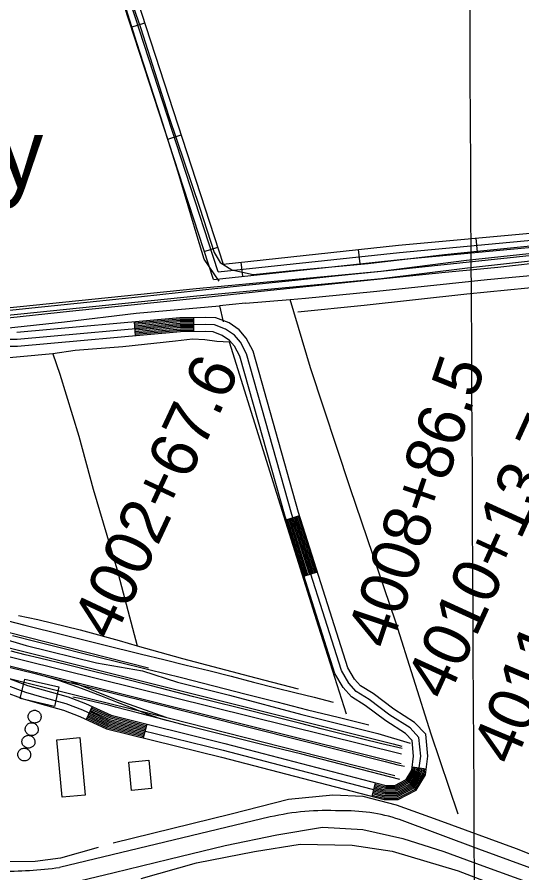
# Model space of a CAD drawing. Extents: x 3445503 to 3483459, y 540493 to 566012.
# Drawn here: x 3469745 to 3470815, y 553015 to 554828 of the extents above; entities that cross this region are included whole.
import ezdxf

# ---------------------------------------------------------------- set-up
doc = ezdxf.new("R2010")
doc.units = 0
for name, color, linetype in [('V-BLDG-OTLN', 7, 'Continuous'), ('V-DOMW-TANK', 7, 'Continuous'), ('V-DTCH-CNTR', 7, 'Continuous'), ('V-GRID-MAJR', 7, 'Continuous'), ('V-LEVE-TOET', 7, 'Continuous'), ('V-RAIL-TRAK', 7, 'Continuous'), ('V-ROAD-CNTR', 7, 'Continuous'), ('V-SURV-IDEN', 7, 'Continuous'), ('V-TOPO-GNAM-IDEN', 7, 'Continuous'), ('V-TOPO-SHOR', 7, 'Continuous')]:
    doc.layers.add(name, color=color, linetype=linetype)

msp = doc.modelspace()

# ---------------------------------------------------------------- linework, layer by layer
at = {"layer": 'V-BLDG-OTLN'}
for points in [[(3469833.551, 553408.933), (3469824.194, 553367.526), (3469751.713, 553383.908), (3469761.756, 553425.157)], [(3469878.085, 553301.382), (3469889.384, 553179.4180000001), (3469840.723, 553174.91), (3469829.4220000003, 553296.8740000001)], [(3470024.412, 553253.463), (3470030.055, 553193.448), (3469987.647, 553189.461), (3469982.006, 553249.478)]]:
    msp.add_lwpolyline(points, close=True, dxfattribs=at)
at = {"layer": 'V-DOMW-TANK'}
for points in [[(3469795.739, 553343.35), (3469795.751, 553341.414), (3469795.057, 553339.837), (3469794.174, 553338.359), (3469793.117, 553337.001), (3469791.901, 553335.778), (3469790.545, 553334.713), (3469789.068, 553333.827), (3469787.494, 553333.1240000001), (3469785.847, 553332.622), (3469784.149, 553332.325), (3469782.429, 553332.2390000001), (3469780.711, 553332.3640000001), (3469779.019, 553332.698), (3469777.383, 553333.2390000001), (3469775.824, 553333.974), (3469774.3680000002, 553334.894), (3469773.037, 553335.987), (3469771.847, 553337.234), (3469770.821, 553338.6190000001), (3469769.971, 553340.118), (3469769.311, 553341.709), (3469768.853, 553343.37), (3469768.599, 553345.074), (3469768.64, 553346.7660000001), (3469768.8880000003, 553348.441), (3469769.34, 553350.071), (3469769.991, 553351.636), (3469770.829, 553353.104), (3469771.845, 553354.46), (3469773.018, 553355.681), (3469774.335, 553356.746), (3469775.773, 553357.639), (3469777.311, 553358.3470000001), (3469778.923, 553358.861), (3469780.59, 553359.1730000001), (3469782.2770000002, 553359.277), (3469783.967, 553359.169), (3469785.63, 553358.853), (3469787.242, 553358.335), (3469788.776, 553357.62), (3469790.211, 553356.721), (3469791.524, 553355.654), (3469792.693, 553354.431), (3469793.705, 553353.072), (3469794.541, 553351.601), (3469795.188, 553350.036), (3469795.636, 553348.404), (3469795.878, 553346.729), (3469795.913, 553345.035)], [(3469789.488, 553316.824), (3469789.503, 553314.889), (3469788.808, 553313.312), (3469787.928, 553311.829), (3469786.869, 553310.471), (3469785.6520000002, 553309.251), (3469784.2970000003, 553308.188), (3469782.8200000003, 553307.301), (3469781.2430000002, 553306.598), (3469779.599, 553306.0970000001), (3469777.901, 553305.8), (3469776.18, 553305.714), (3469774.4620000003, 553305.839), (3469772.771, 553306.172), (3469771.136, 553306.711), (3469769.578, 553307.448), (3469768.12, 553308.368), (3469766.788, 553309.459), (3469765.598, 553310.709), (3469764.572, 553312.091), (3469763.722, 553313.5920000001), (3469763.063, 553315.182), (3469762.6040000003, 553316.8420000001), (3469762.352, 553318.546), (3469762.3910000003, 553320.242), (3469762.639, 553321.9130000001), (3469763.092, 553323.546), (3469763.7430000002, 553325.108), (3469764.583, 553326.579), (3469765.596, 553327.932), (3469766.772, 553329.153), (3469768.0870000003, 553330.218), (3469769.526, 553331.113), (3469771.062, 553331.822), (3469772.674, 553332.336), (3469774.339, 553332.647), (3469776.029, 553332.747), (3469777.718, 553332.6410000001), (3469779.381, 553332.325), (3469780.9930000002, 553331.807), (3469782.525, 553331.0970000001), (3469783.963, 553330.1950000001), (3469785.276, 553329.128), (3469786.447, 553327.906), (3469787.4590000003, 553326.5480000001), (3469788.292, 553325.073), (3469788.9390000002, 553323.509), (3469789.3880000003, 553321.876), (3469789.63, 553320.201), (3469789.664, 553318.51)], [(3469782.597, 553290.292), (3469782.611, 553288.357), (3469781.917, 553286.78), (3469781.034, 553285.299), (3469779.975, 553283.939), (3469778.761, 553282.719), (3469777.403, 553281.656), (3469775.926, 553280.769), (3469774.3540000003, 553280.067), (3469772.705, 553279.567), (3469771.007, 553279.2660000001), (3469769.285, 553279.182), (3469767.569, 553279.307), (3469765.879, 553279.6410000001), (3469764.2430000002, 553280.179), (3469762.684, 553280.914), (3469761.228, 553281.836), (3469759.895, 553282.928), (3469758.707, 553284.177), (3469757.681, 553285.557), (3469756.8310000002, 553287.058), (3469756.171, 553288.65), (3469755.711, 553290.311), (3469755.4590000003, 553292.015), (3469755.498, 553293.708), (3469755.745, 553295.382), (3469756.198, 553297.014), (3469756.849, 553298.576), (3469757.6890000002, 553300.047), (3469758.705, 553301.403), (3469759.878, 553302.621), (3469761.193, 553303.686), (3469762.633, 553304.579), (3469764.169, 553305.29), (3469765.7830000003, 553305.804), (3469767.446, 553306.113), (3469769.1350000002, 553306.215), (3469770.825, 553306.109), (3469772.49, 553305.794), (3469774.1, 553305.275), (3469775.636, 553304.563), (3469777.071, 553303.664), (3469778.38, 553302.595), (3469779.553, 553301.3740000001), (3469780.565, 553300.014), (3469781.401, 553298.542), (3469782.046, 553296.977), (3469782.494, 553295.345), (3469782.734, 553293.671), (3469782.771, 553291.978)], [(3469773.772, 553263.101), (3469773.786, 553261.164), (3469773.09, 553259.587), (3469772.207, 553258.108), (3469771.151, 553256.746), (3469769.934, 553255.525), (3469768.578, 553254.462), (3469767.102, 553253.576), (3469765.531, 553252.873), (3469763.88, 553252.371), (3469762.182, 553252.074), (3469760.4620000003, 553251.988), (3469758.744, 553252.113), (3469757.052, 553252.447), (3469755.418, 553252.986), (3469753.859, 553253.721), (3469752.401, 553254.643), (3469751.0700000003, 553255.734), (3469749.88, 553256.984), (3469748.856, 553258.366), (3469748.004, 553259.865), (3469747.347, 553261.456), (3469746.886, 553263.117), (3469746.634, 553264.821), (3469746.673, 553266.515), (3469746.923, 553268.188), (3469747.373, 553269.8200000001), (3469748.022, 553271.383), (3469748.864, 553272.854), (3469749.88, 553274.209), (3469751.054, 553275.428), (3469752.3680000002, 553276.495), (3469753.806, 553277.39), (3469755.344, 553278.096), (3469756.958, 553278.612), (3469758.6210000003, 553278.922), (3469760.308, 553279.022), (3469762, 553278.916), (3469763.663, 553278.6), (3469765.275, 553278.082), (3469766.813, 553277.3690000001), (3469768.244, 553276.47), (3469769.557, 553275.401), (3469770.7290000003, 553274.181), (3469771.74, 553272.823), (3469772.576, 553271.348), (3469773.221, 553269.786), (3469773.6720000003, 553268.151), (3469773.911, 553266.476), (3469773.946, 553264.784)]]:
    msp.add_lwpolyline(points, close=True, dxfattribs=at)
at = {"layer": 'V-DTCH-CNTR'}
for points in [[(3469961.3540000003, 554936.366), (3470006.4620000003, 554806.06), (3470066.546, 554617.8), (3470132.383, 554423.363), (3470162.683, 554329.234), (3470175.815, 554308.081), (3470200.307, 554292.719), (3470246.014, 554282.71), (3470336.163, 554291.721), (3470489.525, 554306.42), (3470651.15, 554325.331), (3470727.8310000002, 554332.679), (3470876.004, 554347.853)], [(3471246.198, 554316.486), (3471138.61, 554296.112), (3470914.365, 554262.187), (3470698.8310000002, 554241.2930000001), (3470480.733, 554216.748), (3470340.3310000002, 554202.672)]]:
    msp.add_lwpolyline(points, dxfattribs=at)
at = {"layer": 'V-GRID-MAJR'}
msp.add_spline([(3470751.588, 545992.676), (3470719.8680000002, 552050.556), (3470688.132, 558111.519), (3470656.395, 564172.4990000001), (3470656.379, 564175.566)], degree=3, dxfattribs=at)
at = {"layer": 'V-LEVE-TOET'}
msp.add_lwpolyline([(3470007.92, 553002.601), (3470125.33, 553036.049), (3470248.234, 553060.2490000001), (3470345.6580000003, 553075.731), (3470455.611, 553073.505), (3470540.097, 553061.015), (3470680.559, 553018.775), (3470823.4420000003, 552964.167)], dxfattribs=at)
at = {"layer": 'V-RAIL-TRAK'}
for points in [[(3470910.447, 554331.037), (3470517.35, 554289.087), (3470419.312, 554279.036), (3470321.284, 554268.866), (3470223.269, 554258.576), (3470125.268, 554248.1680000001), (3470009.0670000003, 554235.751), (3469892.839, 554223.59), (3469776.5840000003, 554211.681), (3469661.9960000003, 554199.66), (3469547.39, 554187.81), (3469432.768, 554176.128), (3469318.127, 554164.616), (3469194.985, 554151.456), (3469071.828, 554138.412), (3468948.659, 554125.487), (3468825.4760000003, 554112.681), (3468737.412, 554103.274), (3468649.3200000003, 554094.134)], [(3468406.865, 554053.975), (3468802.627, 554094.8200000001), (3468914.022, 554106.686), (3469025.435, 554118.385), (3469136.864, 554129.9130000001), (3469248.313, 554141.273), (3469705.232, 554188.838), (3469856.308, 554204.964), (3470007.424, 554220.74), (3470158.575, 554236.169), (3470282.09, 554249.3420000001), (3470405.625, 554262.304), (3470529.185, 554275.059), (3470652.7630000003, 554287.607), (3470690.0700000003, 554291.025), (3470727.358, 554294.648), (3470764.623, 554298.476), (3470801.87, 554302.508), (3470839.092, 554306.745)], [(3469703.505, 553554.5700000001), (3469761.539, 553539.917), (3469843.918, 553519.093), (3469926.348, 553498.457), (3470008.821, 553478.01), (3470056.392, 553466.639), (3470103.912, 553455.062), (3470151.382, 553443.28), (3470198.8000000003, 553431.289), (3470246.166, 553419.091), (3470293.477, 553406.688), (3470334.148, 553396.841), (3470374.762, 553386.774), (3470415.322, 553376.486)], [(3469735.3540000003, 553517.5160000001), (3469785.8370000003, 553504.734), (3469836.359, 553492.1140000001), (3469886.9220000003, 553479.656), (3469955.8510000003, 553462.91), (3470024.722, 553445.9180000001), (3470093.5300000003, 553428.682), (3470162.2800000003, 553411.202), (3470230.965, 553393.479), (3470295.879, 553376.841), (3470360.866, 553360.481), (3470425.921, 553344.404), (3470491.043, 553328.604)], [(3470561.525, 553278.328), (3470518.48, 553288.457), (3470475.484, 553298.796), (3470432.538, 553309.337), (3470389.642, 553320.087), (3470346.798, 553331.039), (3470304.009, 553342.199), (3470211.772, 553364.979), (3470119.616, 553388.0920000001), (3470027.546, 553411.54), (3469968.842, 553426.329), (3469910.109, 553440.9940000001), (3469851.346, 553455.541), (3469792.554, 553469.969), (3469762.428, 553477.105), (3469732.3370000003, 553484.3910000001)], [(3469719.017, 553452.561), (3469751.373, 553444.939), (3469783.664, 553437.031), (3469802.094, 553432.348), (3469848.028, 553420.373), (3469905.544, 553406.2170000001), (3469963.054, 553392.027), (3470020.556, 553377.801), (3470247.87, 553320.332), (3470340.419, 553297.444), (3470432.915, 553274.332), (3470525.3510000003, 553251.001), (3470538.9250000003, 553247.227), (3470552.5810000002, 553243.76), (3470566.309, 553240.595)], [(3469802.094, 553432.348), (3469816.366, 553428.053), (3469830.588, 553423.586), (3469844.756, 553418.943), (3469858.864, 553414.131), (3469872.914, 553409.148), (3469886.899, 553403.991), (3469922.072, 553390.337), (3469957.213, 553376.601), (3469992.326, 553362.787), (3470006.281, 553357.231), (3470020.3310000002, 553351.917), (3470034.468, 553346.85), (3470048.693, 553342.027), (3470062.9990000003, 553337.452)], [(3470556.827, 553212.419), (3470348.9590000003, 553265.954), (3470266.791, 553286.088), (3470184.707, 553306.555), (3470102.705, 553327.357), (3470062.9990000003, 553337.452), (3470003.3140000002, 553352.8910000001), (3469953.715, 553366.029), (3469938.751, 553370.064), (3469923.727, 553373.867), (3469908.647, 553377.441), (3469893.514, 553380.783), (3469878.3370000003, 553383.894), (3469863.114, 553386.7710000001)]]:
    msp.add_lwpolyline(points, dxfattribs=at)
at = {"layer": 'V-ROAD-CNTR'}
for p, q in [((3469987.273987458, 554807.0003596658), (3470015.801930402, 554816.2833411)), ((3470064.639832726, 554569.2728351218), (3470093.166775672, 554578.555816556)), ((3470717.46652707, 554359.7742541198), (3470720.234521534, 554329.902313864)), ((3470142.004677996, 554331.5453105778), (3470170.5326209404, 554340.8292920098)), ((3470468.4430251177, 554335.4713027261), (3470471.634018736, 554305.641362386)), ((3470219.86252228, 554308.875355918), (3470223.0535158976, 554279.045415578)), ((3469996.5079689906, 554152.64466838), (3469993.8239743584, 554182.52460862)), ((3470119.8997222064, 554161.4336508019), (3470119.6567226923, 554191.4325908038)), ((3470315.4203311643, 553762.8824479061), (3470344.00727399, 553771.9824297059)), ((3470353.336255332, 553643.7716861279), (3470381.9231981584, 553652.871667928)), ((3469904.1701536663, 553367.234239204), (3469891.612178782, 553339.989293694)), ((3470019.9639220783, 553329.9693137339), (3470012.761936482, 553300.8463719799)), ((3470582.8227963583, 553239.2284952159), (3470612.563736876, 553235.300503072)), ((3470504.4929530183, 553205.828562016), (3470496.9209681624, 553176.8006200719))]:
    msp.add_line(p, q, dxfattribs=at)
for points in [[(3468138.8066844, 554033.163907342), (3468295.995370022, 554064.426844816), (3468789.168383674, 554118.576736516), (3469204.1435537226, 554160.2836531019), (3469751.769458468, 554215.095543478), (3470124.766712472, 554253.411466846), (3470516.169929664, 554290.02939361), (3470698.2865654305, 554312.8133480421), (3470863.4712350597, 554331.1123114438), (3471003.3649552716, 554347.608278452), (3471107.484747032, 554365.037243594), (3471215.029531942, 554386.805200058), (3471325.3093113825, 554412.738148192), (3471414.396133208, 554432.097109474), (3471545.65987068, 554474.2730251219), (3471679.9806020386, 554520.0489335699), (3471868.8832242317, 554605.7927620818), (3472145.3916712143, 554763.3564469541), (3472596.50276899, 555045.7928820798), (3473094.633772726, 555368.203237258), (3473177.9566060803, 555426.5551205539), (3473377.13120773, 555552.8458679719), (3473631.614698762, 555713.7455461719), (3473954.2560534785, 555918.9201358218)], [(3468297.7413665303, 554048.5228766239), (3468790.8413803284, 554102.6647683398), (3469205.7405505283, 554144.363684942), (3469753.38345524, 554199.1775753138), (3470126.329709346, 554237.487498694), (3470517.908926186, 554274.1224254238), (3470700.1605616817, 554296.923379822), (3470865.289231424, 554315.2153432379), (3471005.6239507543, 554331.7643101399), (3471110.3937412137, 554349.3012750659), (3471218.448525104, 554371.1732313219), (3471328.8393043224, 554397.132179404), (3471418.552124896, 554416.627140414), (3471550.6878606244, 554459.0830555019), (3471685.8815902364, 554505.155963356), (3471876.1662096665, 554591.527790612), (3472153.6016547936, 554749.619474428), (3472605.0957518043, 555032.2959090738), (3473103.5727548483, 555354.9302638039), (3473186.834588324, 555413.2391471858), (3473385.690190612, 555539.3278950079), (3473640.182681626, 555700.233573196), (3473962.8420363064, 555905.4191628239)], [(3470161.2416395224, 554272.4324288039), (3469951.7220585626, 554916.2461411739), (3469914.669132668, 555036.7319002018), (3469882.199197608, 555135.280703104), (3469708.482545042, 555681.6506103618)], [(3470171.7416185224, 554288.641396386), (3469966.02302996, 554920.7721321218), (3469928.962104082, 555041.283891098), (3469896.470169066, 555139.9006938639), (3469741.0724798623, 555628.6537163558)], [(3470182.4535970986, 554304.1983652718), (3469980.324001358, 554925.29812307), (3469975.4780110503, 554941.0530915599)], [(3470171.7416185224, 554288.641396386), (3470555.6288507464, 554329.7133142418), (3470865.2262315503, 554358.4022568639)], [(3470182.368597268, 554304.86436394), (3470554.1388537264, 554344.63928439), (3470863.8422343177, 554373.3382269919)], [(3470161.2416395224, 554272.4324288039), (3470557.118847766, 554314.7873440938), (3470866.610228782, 554343.4662867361)], [(3469720.021521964, 553413.7301462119), (3469762.694436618, 553397.800178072), (3469796.699368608, 553387.965197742), (3469848.417265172, 553373.8182260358), (3469884.14319372, 553359.9482537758), (3469939.582082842, 553334.3953048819), (3470182.0445979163, 553274.4354248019), (3470525.0939118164, 553184.9536037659), (3470549.66686267, 553185.2616031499), (3470580.484801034, 553201.394570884), (3470596.3857692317, 553227.363518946), (3470600.9627600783, 553262.0194496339), (3470597.123767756, 553301.819370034), (3470578.26180548, 553321.865329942), (3470535.687890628, 553349.0122756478), (3470491.3689792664, 553382.1012094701), (3470463.7150345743, 553399.1741753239), (3470448.464065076, 553416.6401403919), (3470432.8580962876, 553443.4080868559), (3470327.548306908, 553774.2364251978), (3470231.4194991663, 554114.963743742), (3470218.46752507, 554139.3776949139), (3470205.876550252, 554154.0146656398), (3470187.3425873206, 554166.9066398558), (3470163.6046347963, 554176.1536213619), (3470144.9866720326, 554176.6366203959), (3470091.065779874, 554176.2006212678), (3469745.4684710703, 554145.1516833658), (3469682.476597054, 554145.0796835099)], [(3469716.0545298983, 553399.200175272), (3469757.981446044, 553383.5482065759), (3469792.636376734, 553373.5252266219), (3469843.711274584, 553359.5542545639), (3469878.284205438, 553346.1322814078), (3469934.597092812, 553320.1763333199), (3470178.350605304, 553259.897453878), (3470523.2619154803, 553169.9296338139), (3470553.443855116, 553170.3076330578), (3470591.112779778, 553190.0275936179), (3470610.8397403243, 553222.2445291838), (3470616.0577298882, 553261.7544501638), (3470611.5617388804, 553308.363356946), (3470587.903786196, 553333.5073066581), (3470544.218873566, 553361.362250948), (3470499.8119623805, 553394.5171846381), (3470473.5230149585, 553410.7471521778), (3470460.703040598, 553425.429122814), (3470446.650068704, 553449.5340746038), (3470341.91727817, 553778.5494165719), (3470245.420471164, 554120.578732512), (3470230.9325001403, 554147.8886778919), (3470216.005529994, 554165.240643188), (3470194.446573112, 554180.237613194), (3470166.610628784, 554191.080591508), (3470145.1206717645, 554191.6385903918), (3470090.33278134, 554191.1955912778), (3469744.787472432, 554160.150653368)], [(3470119.680722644, 554188.4325968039), (3470090.479781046, 554188.196597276), (3469994.0909738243, 554179.5366145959)], [(3470119.7047225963, 554185.4326028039), (3470090.6257807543, 554185.1976032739), (3469994.3599732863, 554176.5486205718)], [(3470119.729722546, 554182.432608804), (3470090.7727804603, 554182.198609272), (3469994.6279727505, 554173.5606265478)], [(3470119.753722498, 554179.432614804), (3470090.918780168, 554179.1996152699), (3469994.896972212, 554170.5726325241)], [(3470119.7777224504, 554176.4326208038), (3470091.065779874, 554176.2006212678), (3469995.1649716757, 554167.5846385)], [(3469723.98851403, 553428.260117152), (3469767.4074271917, 553412.0521495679), (3469800.7623604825, 553402.4051688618), (3469853.1232557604, 553388.0821975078), (3469890.002182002, 553373.7642261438), (3469944.567072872, 553348.614276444), (3470185.7385905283, 553288.973395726), (3470526.925908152, 553199.9775737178), (3470545.889870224, 553200.2155732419), (3470569.8568222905, 553212.7615481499), (3470581.93179814, 553232.482508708), (3470585.867790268, 553262.2844491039), (3470582.685796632, 553295.275383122), (3470568.6198247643, 553310.223353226), (3470527.15690769, 553336.6623003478), (3470482.925996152, 553369.6852343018), (3470453.90705419, 553387.6011984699), (3470436.2250895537, 553407.8511579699), (3470419.066123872, 553437.282099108), (3470313.1793356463, 553769.9234338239), (3470217.418527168, 554109.348754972), (3470206.0025500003, 554130.866711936), (3470195.74757051, 554142.788688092), (3470180.238601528, 554153.575666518), (3470160.5986408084, 554161.226651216), (3470144.8526723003, 554161.6346503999), (3470091.798778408, 554161.205651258), (3469746.149469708, 554130.1527133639), (3469682.6705966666, 554130.0797135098)], [(3470119.801722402, 554173.4326268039), (3470091.21277958, 554173.2016272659), (3469995.43297114, 554164.5966444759)], [(3470119.825722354, 554170.4326328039), (3470091.3587792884, 554170.2026332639), (3469995.701970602, 554161.6086504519)], [(3470119.8507223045, 554167.432638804), (3470091.505778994, 554167.203639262), (3469995.969970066, 554158.6206564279)], [(3470119.8747222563, 554164.432644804), (3470091.6517787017, 554164.2046452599), (3469996.238969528, 554155.6326624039)], [(3470356.194249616, 553644.6826843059), (3470318.279325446, 553763.793446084)], [(3470359.0532438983, 553645.5926824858), (3470321.138319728, 553764.7034442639)], [(3470361.91223818, 553646.5026806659), (3470323.9973140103, 553765.6134424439)], [(3470364.7702324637, 553647.4126788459), (3470326.8553082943, 553766.523440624)], [(3470367.629226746, 553648.322677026), (3470329.714302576, 553767.4334388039)], [(3470370.4882210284, 553649.2326752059), (3470332.573296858, 553768.3434369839)], [(3470373.346215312, 553650.1426733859), (3470335.431291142, 553769.253435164)], [(3470376.2052095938, 553651.052671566), (3470338.2902854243, 553770.1634333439)], [(3470379.064203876, 553651.9626697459), (3470341.149279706, 553771.0734315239)], [(3469338.7252845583, 553623.2317272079), (3470023.5699148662, 553449.024075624)], [(3469371.2352195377, 553580.4508127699), (3470542.178877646, 553288.0093976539), (3470561.090839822, 553282.9964076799)], [(3469352.808256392, 553565.6648423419), (3470560.094841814, 553267.2354392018)], [(3469320.64432072, 553555.3218630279), (3470559.3998432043, 553246.467480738)], [(3469445.3010714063, 553477.3420189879), (3469660.7096405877, 553443.7680861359), (3469898.636164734, 553383.99120569), (3470068.57282486, 553342.212289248), (3470546.1208697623, 553220.7695321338)], [(3470061.544838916, 553343.9402857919), (3469959.7740424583, 553379.745214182), (3469911.151139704, 553399.223175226), (3469860.170241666, 553419.6151344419)], [(3469900.4031612, 553359.0602555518), (3469941.576078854, 553340.083293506), (3470017.8029264, 553321.232331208)], [(3469901.65815869, 553361.7852501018), (3469942.5730768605, 553342.9272878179), (3470018.5239249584, 553324.1443253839)], [(3469902.914156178, 553364.509244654), (3469943.5700748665, 553345.770282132), (3470019.2439235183, 553327.0563195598)], [(3469892.8681762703, 553342.713288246), (3469935.5940908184, 553323.020327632), (3470013.4819350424, 553303.7583661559)], [(3469894.124173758, 553345.4372827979), (3469936.5910888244, 553325.8633219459), (3470014.2019336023, 553306.670360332)], [(3469895.379171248, 553348.1622773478), (3469937.58808683, 553328.707316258), (3470014.9229321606, 553309.582354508)], [(3469896.635168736, 553350.8862718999), (3469938.585084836, 553331.55131057), (3470015.6429307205, 553312.4953486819)], [(3469897.891166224, 553353.6112664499), (3469939.582082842, 553334.3953048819), (3470016.3629292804, 553315.4073428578)], [(3469899.147163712, 553356.3362609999), (3469940.579080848, 553337.2392991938), (3470017.0829278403, 553318.319337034)], [(3470497.678966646, 553179.7036142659), (3470523.6289147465, 553172.9346278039), (3470552.688856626, 553173.298627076), (3470588.987784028, 553192.300589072), (3470607.948746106, 553223.2685271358), (3470609.5907428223, 553235.6925022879)], [(3470498.435965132, 553182.6056084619), (3470523.994914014, 553175.939621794), (3470551.9328581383, 553176.289621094), (3470586.8617882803, 553194.5745845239), (3470605.0577518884, 553224.2925250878), (3470606.6157487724, 553236.0855015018)], [(3470499.1939636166, 553185.5086026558), (3470524.3609132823, 553178.9436157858), (3470551.1778596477, 553179.279615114), (3470584.735792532, 553196.847579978), (3470602.167757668, 553225.315523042), (3470603.64175472, 553236.478500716)], [(3470499.950962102, 553188.4115968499), (3470524.727912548, 553181.948609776), (3470550.4218611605, 553182.2706091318), (3470582.610796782, 553199.1215754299), (3470599.2767634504, 553226.339520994), (3470600.667760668, 553236.8714999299)], [(3470500.707960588, 553191.314591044), (3470525.0939118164, 553184.9536037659), (3470549.66686267, 553185.2616031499), (3470580.484801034, 553201.394570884), (3470596.3857692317, 553227.363518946), (3470597.693766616, 553237.2644991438)], [(3470501.4649590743, 553194.217585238), (3470525.4599110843, 553187.9585977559), (3470548.91186418, 553188.252597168), (3470578.3588052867, 553203.6675663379), (3470593.494775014, 553228.3875168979), (3470594.719772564, 553237.657498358)], [(3470502.22195756, 553197.120579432), (3470525.82691035, 553190.9635917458), (3470548.155865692, 553191.2435911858), (3470576.233809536, 553205.94156179), (3470590.6037807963, 553229.4115148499), (3470591.745778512, 553238.0504975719)], [(3470502.9799560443, 553200.0235736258), (3470526.1929096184, 553193.9675857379), (3470547.400867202, 553194.2335852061), (3470574.1078137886, 553208.2145572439), (3470587.7137865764, 553230.434512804), (3470588.77178446, 553238.4434967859)], [(3470503.73695453, 553202.925567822), (3470526.558908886, 553196.9725797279), (3470546.6448687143, 553197.2245792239), (3470571.98181804, 553210.488552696), (3470584.8227923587, 553231.458510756), (3470585.7967904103, 553238.8364959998)], [(3470281.881398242, 553133.233707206), (3469835.10829179, 553026.233921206)], [(3472094.500772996, 552543.408886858), (3471481.999998, 552778.403416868), (3471023.557914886, 552955.6820623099), (3470724.167513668, 553064.7988440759), (3470555.873850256, 553127.8337180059)]]:
    msp.add_lwpolyline(points, dxfattribs=at)
for centre, radius, start, end in [((3470401.8342155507, 552607.5892670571), 539.1574498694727, 87.09251468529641, 102.85485079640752), ((3470439.6657859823, 552769.3480138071), 376.85051985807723, 72.03919469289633, 91.59413913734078), ((3469728.629471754, 553764.4368242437), 745.84265443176, 268.34329586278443, 278.2077625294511)]:
    msp.add_arc(centre, radius, start, end, dxfattribs=at)
at = {"layer": 'V-TOPO-SHOR'}
for points in [[(3470173.433, 554268.753), (3470141.955, 554315.169), (3470127.048, 554364.308), (3470086.5670000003, 554499.837), (3470049.867, 554616.208), (3469999.363, 554773.433), (3469954.504, 554916.091)], [(3470229.753, 554222.2980000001), (3470323.8140000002, 554229.732), (3470356.895, 554232.348), (3470500.792, 554247.05), (3470628.554, 554260.334), (3470741.472, 554272.208), (3470878.926, 554284.922), (3471027.953, 554304.185), (3471217.147, 554338.555), (3471230.092, 554340.906)], [(3470679.953, 553139.115), (3470623.071, 553308.507), (3470548.213, 553546.212), (3470451.023, 553830.882), (3470366.9960000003, 554084.66), (3470323.8140000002, 554229.732)], [(3469023.7660000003, 554095.846), (3469225.098, 554115.526), (3469396.735, 554133.677), (3469558.732, 554145.9400000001), (3469621.294, 554156.123), (3469720.643, 554169.181), (3469845.823, 554182.444), (3469997.436, 554201.083), (3470174.265, 554216.046)], [(3470229.753, 554222.2980000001), (3470174.265, 554216.046), (3470182.416, 554182.233)], [(3470443.316, 553350.876), (3470384.361, 553537.691), (3470295.596, 553818.553), (3470195.719, 554139.303), (3470168.989, 554140.706), (3470143.19, 554144.116), (3470116.699, 554145.844), (3470081.214, 554141.689), (3469969.592, 554129.178), (3469868.259, 554121.917), (3469820.927, 554114.682), (3469751.48, 554108.075), (3469695.991, 554103.0920000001)], [(3469820.927, 554114.682), (3469836.1210000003, 554071.535), (3469875.912, 553940.108), (3469906.509, 553827.982), (3469956.282, 553659.178), (3469999.468, 553495.733)], [(3469747.83, 553560.012), (3469789.224, 553551.9450000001), (3469879.168, 553529.409), (3469961.359, 553507.456), (3469999.468, 553495.733), (3470095.988, 553469.132), (3470251.306, 553427.74), (3470341.256, 553404.558)], [(3469662.1890000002, 553527.281), (3469764.609, 553496.733), (3469913.435, 553459.809), (3470011.295, 553442.9400000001), (3470084.892, 553419.191), (3470195.5470000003, 553391.009), (3470348.9220000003, 553350.2490000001), (3470510.044, 553310.1950000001), (3470578.663, 553289.428)], [(3471883.751, 552650.986), (3471648.818, 552747.136), (3471448.671, 552822.4), (3471208.369, 552912.197), (3471014.721, 552982.345), (3470804.174, 553065.922), (3470637.725, 553126.598), (3470549.647, 553158.188), (3470479.111, 553176.358), (3470414.509, 553179.074), (3470320.295, 553169.931), (3470199.129, 553139.265), (3469948.933, 553077.4130000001)], [(3469576.691, 553006.536), (3469677.735, 552983.485), (3469772.717, 552977.135), (3469842.3680000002, 552989.312), (3469951.301, 553015.361), (3470066.671, 553044.045), (3470186.561, 553072.764), (3470296.164, 553095.591), (3470392.9050000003, 553111.856), (3470478.19, 553106.72), (3470562.9420000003, 553087.372), (3470649.693, 553060.292), (3470732.596, 553029.95), (3470832.3340000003, 552993.93), (3470952.838, 552945.159), (3471080.41, 552900.965), (3471187.308, 552857.9), (3471329.8200000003, 552802.846), (3471445.757, 552759.85), (3471570.13, 552711.757), (3471667.306, 552673.134), (3471815.616, 552612.077)], [(3469917.378, 553068.346), (3469836.932, 553045.98), (3469783.387, 553039.099), (3469705.256, 553037.833), (3469610.528, 553055.026)]]:
    msp.add_lwpolyline(points, dxfattribs=at)

# ---------------------------------------------------------------- texts
at = {"layer": 'V-SURV-IDEN'}
for s, height, rotation, p in [('4002+67.6', 100.00000000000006, 64.90354940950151, (3469948.388246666, 553503.752081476)), ('4008+86.5', 100, 71.3413458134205, (3470536.057090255, 553485.444091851)), ('4010+13.7', 100, 65.41886755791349, (3470655.7452822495, 553376.6708686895)), ('4011+46.0', 99.99999999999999, 67.27193987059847, (3470797.826471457, 553238.9417482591))]:
    msp.add_text(s, height=height, rotation=rotation, dxfattribs=at).set_placement(p)
at = {"layer": 'V-TOPO-GNAM-IDEN'}
msp.add_text('Remy', height=144.99971199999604, rotation=0.6418443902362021, dxfattribs=at).set_placement((3469295.5863708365, 554461.307051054))

doc.saveas('drawing.dxf')
